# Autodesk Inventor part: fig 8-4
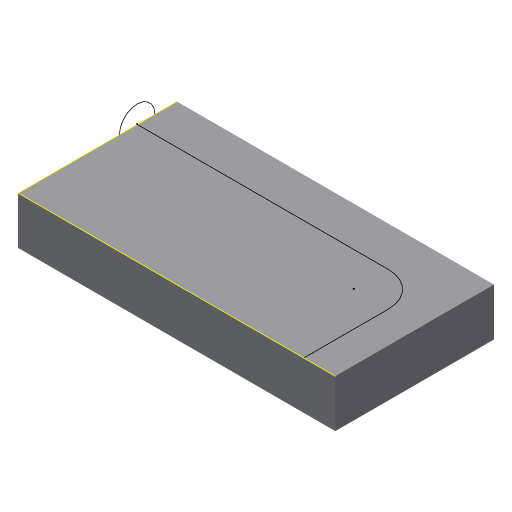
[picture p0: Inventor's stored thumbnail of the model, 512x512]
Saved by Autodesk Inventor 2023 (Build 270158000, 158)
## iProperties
Created: 2009-04
Part Number: fig 8-4
Document SubType Name: Modeling
Designer: Sham
Density: 1 g/cm^3
Material: Generic
Appearance: Default
Author: Sham
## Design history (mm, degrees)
sketch "Sketch1"
  geometry: L1 (-20, 20)-(20, 20); L2 (20, 20)-(20, 0); L3 (20, 0)-(-20, 0); L4 (-20, 0)-(-20, 20)
  constraints: 8 end point
extrude "Extrusion1" new body sketch "Sketch1" distance "d0" = 6; taper "d1" = 0 deg
sketch "Sketch4"
  geometry: L1 (6, 0)-(6, 20) reference; C1 r 2.236 at (6, 15)
  constraints: 1 centre point, 1 point on line
sketch "Sketch5"
  geometry: L1 (-20, 0)-(-20, 20) reference; L2 (20, 0)-(-20, 0) reference; L3 (-20, 15)-(11.667, 15); L4 (16, 10.667)-(16, 0); A1 r 4.333 centre (11.667, 10.667) between (16, 10.667) and (11.667, 15)
  constraints: 4 end point, 2 point on circle, 2 point on line, 1 centre point, 1 tangent
body "Solid1"
